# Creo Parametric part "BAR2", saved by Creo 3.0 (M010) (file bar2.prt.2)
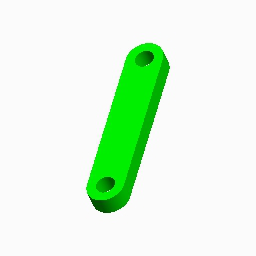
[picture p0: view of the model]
Units: millimeter Newton Second (mmNs); MM, TONNE, SECS

Created from: MMNS_PART_SOLID.PRT

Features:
  1. datum plane "RIGHT"
  2. datum plane "TOP"
  3. datum plane "FRONT"
  4. coordinate system
  5. sketch "Sketch 1"
  6. extrusion "Extrude 1"

Surfaces: 7 plane, 6 cylinder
